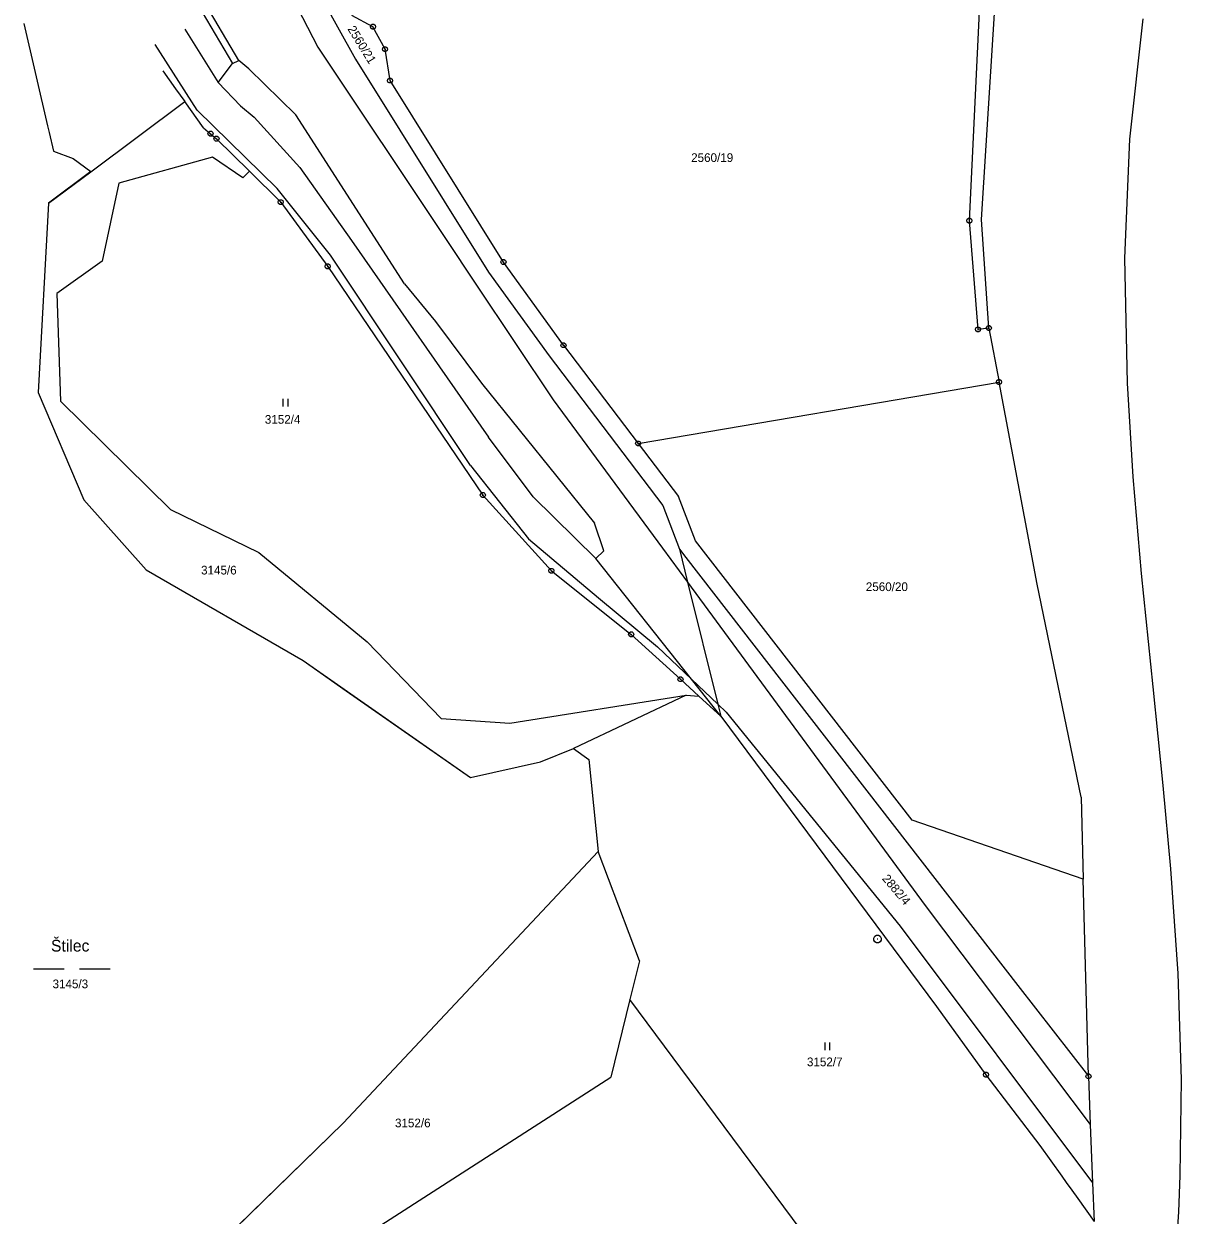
# Model space of a CAD drawing. Extents: x -760611 to -758411, y -1176479 to -1174807.
# Drawn here: x -759708.9 to -759482.8, y -1175743.1 to -1175510.2 of the extents above; entities that cross this region are included whole.
import ezdxf

# ---------------------------------------------------------------- set-up
doc = ezdxf.new("R2010")
doc.units = 0
for name, color, linetype in [('1', 7, 'Continuous'), ('11', 7, 'Continuous'), ('2', 7, 'Continuous'), ('3', 7, 'Continuous'), ('4', 7, 'Continuous'), ('6', 7, 'Continuous'), ('7', 7, 'Continuous'), ('8', 7, 'Continuous')]:
    doc.layers.add(name, color=color, linetype=linetype)

msp = doc.modelspace()

# ---------------------------------------------------------------- linework, layer by layer
at = {"layer": '1'}
for p, q in [((-759666.88, -1175517.39), (-759677.12, -1175499.89)), ((-759652.92, -1175501.24), (-759644.08, -1175517.16)), ((-759524.15, -1175548.73), (-759521.91, -1175501.85)), ((-759521.78, -1175548.52), (-759518.92, -1175502.61)), ((-759640.67, -1175510.81), (-759644.8, -1175508.65)), ((-759677.46, -1175511.27), (-759670.92, -1175521.71)), ((-759638.31, -1175515.21), (-759640.67, -1175510.81)), ((-759637.34, -1175521.34), (-759638.31, -1175515.21)), ((-759670.92, -1175521.71), (-759668.09, -1175517.99)), ((-759668.09, -1175517.99), (-759666.88, -1175517.39)), ((-759644.08, -1175517.16), (-759618.08, -1175558.76)), ((-759681.7, -1175519.43), (-759679.24, -1175522.93)), ((-759679.24, -1175522.93), (-759677.44, -1175525.45)), ((-759670.92, -1175521.71), (-759666.58, -1175526.28)), ((-759615.18, -1175556.8), (-759637.34, -1175521.34)), ((-759695.8, -1175539.16), (-759677.44, -1175525.45)), ((-759673.78, -1175530.58), (-759677.44, -1175525.45)), ((-759666.58, -1175526.28), (-759663.92, -1175528.52)), ((-759663.92, -1175528.52), (-759654.98, -1175538.35)), ((-759673.78, -1175530.58), (-759672.4, -1175531.74)), ((-759672.4, -1175531.74), (-759671.25, -1175532.71)), ((-759671.25, -1175532.71), (-759664.83, -1175539.05)), ((-759672.01, -1175536.31), (-759690.3, -1175541.41)), ((-759666.1, -1175540.35), (-759672.01, -1175536.31)), ((-759704.09, -1175545.3), (-759695.8, -1175539.16)), ((-759664.83, -1175539.05), (-759666.1, -1175540.35)), ((-759658.7, -1175545.1), (-759664.83, -1175539.05)), ((-759654.98, -1175538.35), (-759644.9, -1175552.62)), ((-759690.3, -1175541.41), (-759693.58, -1175556.63)), ((-759704.09, -1175545.3), (-759706.11, -1175582.33)), ((-759658.7, -1175545.1), (-759649.52, -1175557.67)), ((-759520.34, -1175569.71), (-759521.78, -1175548.52)), ((-759522.46, -1175569.99), (-759524.15, -1175548.73)), ((-759644.9, -1175552.62), (-759618.13, -1175591.06)), ((-759693.58, -1175556.63), (-759702.46, -1175562.95)), ((-759649.52, -1175557.67), (-759619.19, -1175602.36)), ((-759603.46, -1175573.07), (-759615.18, -1175556.8)), ((-759618.08, -1175558.76), (-759606.27, -1175575.15)), ((-759702.46, -1175562.95), (-759701.75, -1175584.01)), ((-759520.34, -1175569.71), (-759522.46, -1175569.99)), ((-759520.34, -1175569.71), (-759518.35, -1175580.27)), ((-759603.46, -1175573.07), (-759588.85, -1175592.27)), ((-759606.27, -1175575.15), (-759584.04, -1175604.37)), ((-759588.85, -1175592.27), (-759518.35, -1175580.27)), ((-759510.9, -1175619.77), (-759518.35, -1175580.27)), ((-759706.11, -1175582.33), (-759697.16, -1175603.25)), ((-759701.75, -1175584.01), (-759680.21, -1175605.15)), ((-759609.35, -1175602.71), (-759618.13, -1175591.06)), ((-759588.85, -1175592.27), (-759580.95, -1175602.65)), ((-759697.16, -1175603.25), (-759685.01, -1175616.96)), ((-759619.19, -1175602.36), (-759605.81, -1175617.16)), ((-759597.1, -1175614.76), (-759609.35, -1175602.71)), ((-759584.04, -1175604.37), (-759580.79, -1175612.92)), ((-759577.67, -1175611.28), (-759580.95, -1175602.65)), ((-759680.21, -1175605.15), (-759662.95, -1175613.56)), ((-759535.31, -1175665.87), (-759577.67, -1175611.28)), ((-759662.95, -1175613.56), (-759641.79, -1175631.04)), ((-759580.79, -1175612.92), (-759579.2, -1175619.36)), ((-759580.79, -1175612.92), (-759579.56, -1175614.55)), ((-759578.42, -1175638.36), (-759597.1, -1175614.76)), ((-759579.56, -1175614.55), (-759514.66, -1175698.19)), ((-759685.01, -1175616.96), (-759654.31, -1175634.71)), ((-759605.81, -1175617.16), (-759590.21, -1175629.59)), ((-759579.2, -1175619.36), (-759573.3, -1175643.21)), ((-759502.34, -1175661.42), (-759510.9, -1175619.77)), ((-759590.21, -1175629.59), (-759580.59, -1175638.36)), ((-759641.79, -1175631.04), (-759627.37, -1175646.04)), ((-759654.31, -1175634.71), (-759621.62, -1175657.54)), ((-759580.59, -1175638.36), (-759576.99, -1175641.65)), ((-759572.72, -1175645.55), (-759578.42, -1175638.36)), ((-759613.95, -1175646.92), (-759579.51, -1175641.43)), ((-759579.51, -1175641.43), (-759601.49, -1175651.9)), ((-759579.51, -1175641.43), (-759576.99, -1175641.65)), ((-759575.49, -1175643.02), (-759576.99, -1175641.65)), ((-759575.49, -1175643.02), (-759572.72, -1175645.55)), ((-759573.3, -1175643.21), (-759572.72, -1175645.55)), ((-759627.37, -1175646.04), (-759613.95, -1175646.92)), ((-759572.72, -1175645.55), (-759530.58, -1175702.28)), ((-759607.94, -1175654.48), (-759601.49, -1175651.9)), ((-759601.49, -1175651.9), (-759598.47, -1175654.06)), ((-759621.62, -1175657.54), (-759607.94, -1175654.48)), ((-759598.47, -1175654.06), (-759596.68, -1175672.01)), ((-759502.34, -1175661.42), (-759501.91, -1175677.4)), ((-759501.91, -1175677.4), (-759535.31, -1175665.87)), ((-759596.68, -1175672.01), (-759646.53, -1175725.11)), ((-759588.6, -1175693.39), (-759596.68, -1175672.01)), ((-759500.88, -1175715.95), (-759501.91, -1175677.4)), ((-759588.6, -1175693.39), (-759590.47, -1175700.96)), ((-759514.66, -1175698.19), (-759500.88, -1175715.95)), ((-759590.47, -1175700.96), (-759594.21, -1175716.13)), ((-759524.09, -1175790.32), (-759590.47, -1175700.96)), ((-759530.58, -1175702.28), (-759520.91, -1175715.63)), ((-759643.9, -1175748.13), (-759594.21, -1175716.13)), ((-759520.91, -1175715.63), (-759510.37, -1175729.49)), ((-759500.88, -1175715.95), (-759500.52, -1175725.4)), ((-759646.53, -1175725.11), (-759672.08, -1175750.06)), ((-759500.52, -1175725.4), (-759500.08, -1175736.74)), ((-759510.37, -1175729.49), (-759506.09, -1175735.49)), ((-759506.09, -1175735.49), (-759505.21, -1175736.72)), ((-759505.21, -1175736.72), (-759504.16, -1175738.19)), ((-759500.08, -1175736.74), (-759499.79, -1175744.32)), ((-759504.16, -1175738.19), (-759502.97, -1175739.86)), ((-759502.97, -1175739.86), (-759499.79, -1175744.32))]:
    msp.add_line(p, q, dxfattribs=at)
at = {"layer": '11'}
msp.add_lwpolyline([(-759708.89, -1175510.17), (-759704.26, -1175530.16), (-759703.95, -1175531.51), (-759703.1, -1175535.16), (-759699.22, -1175536.56), (-759695.82, -1175539.14), (-759704.09, -1175545.3), (-759706.11, -1175582.33), (-759697.16, -1175603.25), (-759693.45, -1175607.43), (-759685.01, -1175616.96), (-759654.31, -1175634.71), (-759645.88, -1175640.6), (-759621.62, -1175657.54), (-759607.94, -1175654.48), (-759601.49, -1175651.9), (-759598.47, -1175654.06), (-759596.68, -1175672.01), (-759646.53, -1175725.11), (-759672.08, -1175750.06)], dxfattribs=at)
at = {"layer": '3'}
for p, q in [((-759658.26, -1175583.51), (-759658.26, -1175585.01)), ((-759657.26, -1175585.01), (-759657.26, -1175583.51)), ((-759707.03, -1175694.92), (-759701.03, -1175694.92)), ((-759698.03, -1175694.92), (-759692.03, -1175694.92)), ((-759552.41, -1175709.32), (-759552.41, -1175710.82)), ((-759551.41, -1175710.82), (-759551.41, -1175709.32))]:
    msp.add_line(p, q, dxfattribs=at)
at = {"layer": '4'}
for p, q in [((-759667.76, -1175483.16), (-759651.44, -1175514.84)), ((-759678.43, -1175500.46), (-759668.09, -1175517.99)), ((-759675.01, -1175527.15), (-759683.25, -1175514.3)), ((-759651.44, -1175514.84), (-759626.63, -1175552.03)), ((-759664.91, -1175519.04), (-759666.88, -1175517.39)), ((-759655.76, -1175528.04), (-759664.91, -1175519.04)), ((-759659.41, -1175542.41), (-759675.01, -1175527.15)), ((-759634.54, -1175561.09), (-759655.76, -1175528.04)), ((-759648.96, -1175555.45), (-759659.41, -1175542.41)), ((-759626.63, -1175552.03), (-759620.42, -1175561.3)), ((-759621.6, -1175596.56), (-759648.96, -1175555.45)), ((-759634.54, -1175561.09), (-759628.43, -1175568.44)), ((-759620.42, -1175561.3), (-759605.48, -1175583.72)), ((-759628.43, -1175568.44), (-759619.48, -1175580.51)), ((-759619.48, -1175580.51), (-759597.41, -1175607.86)), ((-759605.48, -1175583.72), (-759584.09, -1175612.7)), ((-759621.6, -1175596.56), (-759610.29, -1175610.92)), ((-759595.58, -1175613.22), (-759597.41, -1175607.86)), ((-759610.29, -1175610.92), (-759596.59, -1175622.45)), ((-759597.1, -1175614.76), (-759595.58, -1175613.22)), ((-759584.09, -1175612.7), (-759579.2, -1175619.36)), ((-759579.2, -1175619.36), (-759532.78, -1175682.57)), ((-759596.59, -1175622.45), (-759585.09, -1175632.03)), ((-759585.09, -1175632.03), (-759578.42, -1175638.36)), ((-759578.42, -1175638.36), (-759573.3, -1175643.21)), ((-759573.3, -1175643.21), (-759571.66, -1175644.76)), ((-759571.66, -1175644.76), (-759537.64, -1175686.59)), ((-759532.78, -1175682.57), (-759500.52, -1175725.4)), ((-759537.64, -1175686.59), (-759500.08, -1175736.74))]:
    msp.add_line(p, q, dxfattribs=at)
at = {"layer": '6'}
for p, q in [((-759490.26, -1175509.28), (-759492.87, -1175532.78)), ((-759492.87, -1175532.78), (-759493.86, -1175556.07)), ((-759493.86, -1175556.07), (-759493.34, -1175580.49)), ((-759493.34, -1175580.49), (-759492.2, -1175598.79)), ((-759492.2, -1175598.79), (-759490.56, -1175617.67)), ((-759490.56, -1175617.67), (-759488.29, -1175639.85)), ((-759488.29, -1175639.85), (-759486.34, -1175659.1)), ((-759486.34, -1175659.1), (-759484.85, -1175675.38)), ((-759484.85, -1175675.38), (-759483.42, -1175695.88)), ((-759483.42, -1175695.88), (-759482.77, -1175716.56)), ((-759482.77, -1175716.56), (-759483, -1175735.33)), ((-759483, -1175735.33), (-759483.28, -1175742.43)), ((-759483.28, -1175742.43), (-759484.17, -1175755.51))]:
    msp.add_line(p, q, dxfattribs=at)
at = {"layer": '8'}
for p, q in [((-759640.79, -1175510.81), (-759640.55, -1175510.81)), ((-759638.43, -1175515.21), (-759638.19, -1175515.21)), ((-759637.46, -1175521.34), (-759637.22, -1175521.34)), ((-759672.52, -1175531.74), (-759672.28, -1175531.74)), ((-759671.37, -1175532.71), (-759671.13, -1175532.71)), ((-759658.82, -1175545.1), (-759658.58, -1175545.1)), ((-759524.27, -1175548.73), (-759524.03, -1175548.73)), ((-759649.64, -1175557.67), (-759649.4, -1175557.67)), ((-759615.3, -1175556.8), (-759615.06, -1175556.8)), ((-759522.58, -1175569.99), (-759522.34, -1175569.99)), ((-759520.46, -1175569.71), (-759520.22, -1175569.71)), ((-759603.58, -1175573.07), (-759603.34, -1175573.07)), ((-759518.47, -1175580.27), (-759518.23, -1175580.27)), ((-759588.97, -1175592.27), (-759588.73, -1175592.27)), ((-759619.31, -1175602.36), (-759619.07, -1175602.36)), ((-759605.93, -1175617.16), (-759605.69, -1175617.16)), ((-759590.33, -1175629.59), (-759590.09, -1175629.59)), ((-759580.71, -1175638.36), (-759580.47, -1175638.36)), ((-759542.15, -1175689.11), (-759542.05, -1175689.11)), ((-759521.03, -1175715.63), (-759520.79, -1175715.63)), ((-759501, -1175715.95), (-759500.76, -1175715.95))]:
    msp.add_line(p, q, dxfattribs=at)
for points in [[(-759640.52, -1175510.33), (-759640.27, -1175510.51), (-759640.17, -1175510.8), (-759640.27, -1175511.09), (-759640.52, -1175511.27), (-759640.83, -1175511.27), (-759641.08, -1175511.09), (-759641.18, -1175510.8), (-759641.08, -1175510.51), (-759640.83, -1175510.33)], [(-759638.16, -1175514.73), (-759637.91, -1175514.91), (-759637.81, -1175515.2), (-759637.91, -1175515.49), (-759638.16, -1175515.67), (-759638.47, -1175515.67), (-759638.72, -1175515.49), (-759638.82, -1175515.2), (-759638.72, -1175514.91), (-759638.47, -1175514.73)], [(-759637.19, -1175520.86), (-759636.94, -1175521.04), (-759636.84, -1175521.33), (-759636.94, -1175521.62), (-759637.19, -1175521.8), (-759637.5, -1175521.8), (-759637.75, -1175521.62), (-759637.85, -1175521.33), (-759637.75, -1175521.04), (-759637.5, -1175520.86)], [(-759672.25, -1175531.26), (-759672, -1175531.44), (-759671.9, -1175531.73), (-759672, -1175532.02), (-759672.25, -1175532.2), (-759672.56, -1175532.2), (-759672.81, -1175532.02), (-759672.91, -1175531.73), (-759672.81, -1175531.44), (-759672.56, -1175531.26)], [(-759671.1, -1175532.23), (-759670.85, -1175532.41), (-759670.75, -1175532.7), (-759670.85, -1175532.99), (-759671.1, -1175533.17), (-759671.41, -1175533.17), (-759671.66, -1175532.99), (-759671.76, -1175532.7), (-759671.66, -1175532.41), (-759671.41, -1175532.23)], [(-759658.55, -1175544.62), (-759658.3, -1175544.8), (-759658.2, -1175545.09), (-759658.3, -1175545.38), (-759658.55, -1175545.56), (-759658.86, -1175545.56), (-759659.11, -1175545.38), (-759659.21, -1175545.09), (-759659.11, -1175544.8), (-759658.86, -1175544.62)], [(-759524, -1175548.25), (-759523.75, -1175548.43), (-759523.65, -1175548.72), (-759523.75, -1175549.01), (-759524, -1175549.19), (-759524.31, -1175549.19), (-759524.56, -1175549.01), (-759524.66, -1175548.72), (-759524.56, -1175548.43), (-759524.31, -1175548.25)], [(-759649.37, -1175557.19), (-759649.12, -1175557.37), (-759649.02, -1175557.66), (-759649.12, -1175557.95), (-759649.37, -1175558.13), (-759649.68, -1175558.13), (-759649.93, -1175557.95), (-759650.03, -1175557.66), (-759649.93, -1175557.37), (-759649.68, -1175557.19)], [(-759615.03, -1175556.32), (-759614.78, -1175556.5), (-759614.68, -1175556.79), (-759614.78, -1175557.08), (-759615.03, -1175557.26), (-759615.34, -1175557.26), (-759615.59, -1175557.08), (-759615.69, -1175556.79), (-759615.59, -1175556.5), (-759615.34, -1175556.32)], [(-759522.31, -1175569.51), (-759522.06, -1175569.69), (-759521.96, -1175569.98), (-759522.06, -1175570.27), (-759522.31, -1175570.45), (-759522.62, -1175570.45), (-759522.87, -1175570.27), (-759522.97, -1175569.98), (-759522.87, -1175569.69), (-759522.62, -1175569.51)], [(-759520.19, -1175569.23), (-759519.94, -1175569.41), (-759519.84, -1175569.7), (-759519.94, -1175569.99), (-759520.19, -1175570.17), (-759520.5, -1175570.17), (-759520.75, -1175569.99), (-759520.85, -1175569.7), (-759520.75, -1175569.41), (-759520.5, -1175569.23)], [(-759603.31, -1175572.59), (-759603.06, -1175572.77), (-759602.96, -1175573.06), (-759603.06, -1175573.35), (-759603.31, -1175573.53), (-759603.62, -1175573.53), (-759603.87, -1175573.35), (-759603.97, -1175573.06), (-759603.87, -1175572.77), (-759603.62, -1175572.59)], [(-759518.2, -1175579.79), (-759517.95, -1175579.97), (-759517.85, -1175580.26), (-759517.95, -1175580.55), (-759518.2, -1175580.73), (-759518.51, -1175580.73), (-759518.76, -1175580.55), (-759518.86, -1175580.26), (-759518.76, -1175579.97), (-759518.51, -1175579.79)], [(-759588.7, -1175591.79), (-759588.45, -1175591.97), (-759588.35, -1175592.26), (-759588.45, -1175592.55), (-759588.7, -1175592.73), (-759589.01, -1175592.73), (-759589.26, -1175592.55), (-759589.36, -1175592.26), (-759589.26, -1175591.97), (-759589.01, -1175591.79)], [(-759619.04, -1175601.88), (-759618.79, -1175602.06), (-759618.69, -1175602.35), (-759618.79, -1175602.64), (-759619.04, -1175602.82), (-759619.35, -1175602.82), (-759619.6, -1175602.64), (-759619.7, -1175602.35), (-759619.6, -1175602.06), (-759619.35, -1175601.88)], [(-759605.66, -1175616.68), (-759605.41, -1175616.86), (-759605.31, -1175617.15), (-759605.41, -1175617.44), (-759605.66, -1175617.62), (-759605.97, -1175617.62), (-759606.22, -1175617.44), (-759606.32, -1175617.15), (-759606.22, -1175616.86), (-759605.97, -1175616.68)], [(-759590.06, -1175629.11), (-759589.81, -1175629.29), (-759589.71, -1175629.58), (-759589.81, -1175629.87), (-759590.06, -1175630.05), (-759590.37, -1175630.05), (-759590.62, -1175629.87), (-759590.72, -1175629.58), (-759590.62, -1175629.29), (-759590.37, -1175629.11)], [(-759580.44, -1175637.88), (-759580.19, -1175638.06), (-759580.09, -1175638.35), (-759580.19, -1175638.64), (-759580.44, -1175638.82), (-759580.75, -1175638.82), (-759581, -1175638.64), (-759581.1, -1175638.35), (-759581, -1175638.06), (-759580.75, -1175637.88)], [(-759541.91, -1175688.39), (-759541.57, -1175688.58), (-759541.38, -1175688.92), (-759541.38, -1175689.31), (-759541.57, -1175689.65), (-759541.91, -1175689.84), (-759542.3, -1175689.84), (-759542.64, -1175689.65), (-759542.83, -1175689.31), (-759542.83, -1175688.92), (-759542.64, -1175688.58), (-759542.3, -1175688.39)], [(-759520.76, -1175715.15), (-759520.51, -1175715.33), (-759520.41, -1175715.62), (-759520.51, -1175715.91), (-759520.76, -1175716.09), (-759521.07, -1175716.09), (-759521.32, -1175715.91), (-759521.42, -1175715.62), (-759521.32, -1175715.33), (-759521.07, -1175715.15)], [(-759500.73, -1175715.47), (-759500.48, -1175715.65), (-759500.38, -1175715.94), (-759500.48, -1175716.23), (-759500.73, -1175716.41), (-759501.04, -1175716.41), (-759501.29, -1175716.23), (-759501.39, -1175715.94), (-759501.29, -1175715.65), (-759501.04, -1175715.47)]]:
    msp.add_lwpolyline(points, close=True, dxfattribs=at)

# ---------------------------------------------------------------- texts
at = {"layer": '2'}
for s, rotation, p in [('2560/21', 301.605, (-759645.71, -1175511.26)), ('2882/4', 310.2566, (-759541.3, -1175677.36))]:
    msp.add_text(s, height=1.7, rotation=rotation, dxfattribs=at).set_placement(p)
for s, p in [('2560/19', (-759578.51, -1175537.25)), ('3152/4', (-759661.8, -1175588.41)), ('3145/6', (-759674.26, -1175617.87)), ('2560/20', (-759544.38, -1175621.11)), ('3145/3', (-759703.28, -1175698.74)), ('3152/7', (-759555.88, -1175713.98)), ('3152/6', (-759636.37, -1175725.92))]:
    msp.add_text(s, height=1.7, dxfattribs=at).set_placement(p)
at = {"layer": '7'}
msp.add_text('Štilec', height=2.3, dxfattribs=at).set_placement((-759703.59, -1175691.57))

doc.saveas('drawing.dxf')
